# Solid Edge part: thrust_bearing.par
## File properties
Title: Thrust bearing
Author: Deepak Maini
Template: Normal.par
Last saved by: CADCIM
Revision: 9
Application: Solid Edge
Accuracy: 0.99
Material: aluminum
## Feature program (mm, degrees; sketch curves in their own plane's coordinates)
sketch for "unnamed RevolvedProtrusion 1" plane through (0, 0, 0) normal (0, -1, 0) x-axis (1, 0, 0)
  line (47.625, 16.8036) -> (66.929, 16.8036)
  line (66.929, 16.8036) -> (73.025, 10.7076)
  line (73.025, 10.7076) -> (73.025, -12.0254)
  line (73.025, -12.0254) -> (66.929, -18.1214)
  line (66.929, -18.1214) -> (47.625, -18.1214)
  line (47.625, -18.1214) -> (47.625, -7.1994)
  line (61.5714, -7.1994) -> (47.625, -7.1994)
  line (61.5714, 5.8816) -> (61.5714, -7.1994)
  line (47.625, 5.8816) -> (61.5714, 5.8816)
  line (47.625, 5.8816) -> (47.625, 16.8036)
revolve "unnamed RevolvedProtrusion 1" add finite 360 deg
sketch for "unnamed RevolvedProtrusion 2" plane through (0, 0, 0) normal (1, 0, 0) x-axis (0, 1, 0)
  line (69.977, 13.7556) -> (73.0652, 13.7556)
  line (73.0652, 13.7556) -> (74.6125, 12.2083)
  line (74.6125, 12.2083) -> (74.6125, -13.4669)
  line (74.6125, -13.4669) -> (73.006, -15.0734)
  line (73.006, -15.0734) -> (69.977, -15.0734)
revolve "unnamed RevolvedProtrusion 2" add full turn 360 deg
sketch for "unnamed RevolvedProtrusion 3" plane through (0, 0, 0) normal (0, -1, 0) x-axis (1, 0, 0)
revolve "unnamed RevolvedProtrusion 3" add full turn 360 deg about sketch line (-54.9674, 10.1232) -> (-54.9674, -18.1214)
pattern "unnamed Pattern 1" of "unnamed RevolvedProtrusion 3"
pattern "unnamed Pattern 2"
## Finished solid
Body 1: solid body, 39 faces, 39 edges, 25 vertices.
  Faces by surface: torus 25, plane 6, cone 4, cylinder 4
  Edges by curve: circle 39
Bounding box of the edges (mm; curved faces can reach further): 149.225 x 149.225 x 34.925, from (-74.6125, -74.6125, -18.1214) to (74.6125, 74.6125, 16.8036).
Cylindrical faces by radius (mm): R47.625 x2, R61.5714 x1, R74.6125 x1
Conical faces (half-angle, radius in mm at the cone's reference point): 45 deg R66.929 x1, 45 deg R73.025 x1, 45 deg R73.0652 x1, 45 deg R74.6125 x1
Toroidal faces (ring radius, tube radius in mm): R-0.1023 r6.604 x25
Planar faces by outward normal: +z 3, -z 3
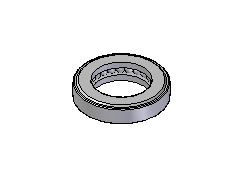
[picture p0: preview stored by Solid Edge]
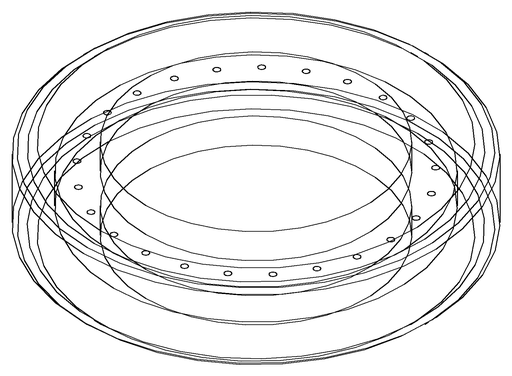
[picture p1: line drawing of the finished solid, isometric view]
